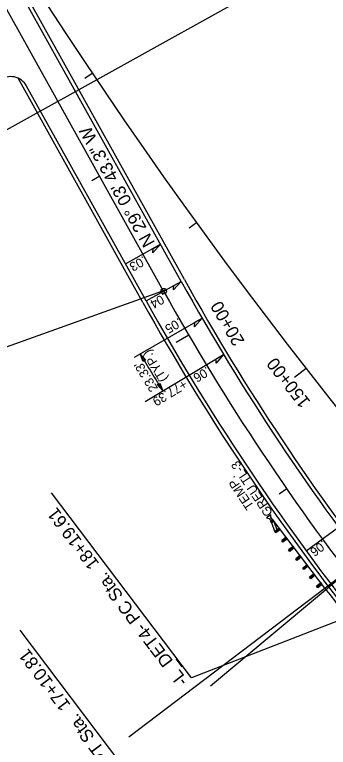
# Model space of a CAD drawing. Extents: x 473658 to 481584, y 489119 to 506230.
# Drawn here: x 476198.9 to 476370.9, y 500835 to 501237.1 of the extents above; entities that cross this region are included whole.
import ezdxf

# ---------------------------------------------------------------- set-up
doc = ezdxf.new("R2010")
doc.units = 0
for name, color, linetype in [('Prop EOT', 7, 'Continuous'), ('Prop Guardrail', 7, 'Continuous'), ('Prop Guardrail Anchor Unit CELL', 7, 'Continuous'), ('Prop Horizontal Alignment', 7, 'Continuous'), ('Prop Horizontal Alignment Direction Label', 7, 'Continuous'), ('Prop Horizontal Alignment Station Label', 7, 'Continuous'), ('Prop Horizontal Alignment Tick Label', 7, 'Continuous'), ('Prop Horizontal Alignment Tick Large', 7, 'Continuous'), ('Prop Horizontal Alignment Tick Small', 7, 'Continuous'), ('Prop Paved Shoulder', 7, 'Continuous'), ('Prop Superelevation  Arrow CELL', 7, 'Continuous'), ('Prop Superelevation Label', 7, 'Continuous'), ('Scratch_Level_5', 7, 'Continuous'), ('Scratch_Level_6', 7, 'Continuous'), ('Sheet Plan And Profile CELL', 7, 'Continuous')]:
    doc.layers.add(name, color=color, linetype=linetype)

msp = doc.modelspace()

# ---------------------------------------------------------------- linework, layer by layer
at = {"layer": 'Prop EOT'}
for p, q in [((476290.24, 501090.74), (475837.09, 501906.16)), ((476271.01, 501080.05), (476205.48, 501197.96))]:
    msp.add_line(p, q, dxfattribs=at)
for centre, radius, start, end in [((476196.74, 501193.11), 10, 29.062, 127.5691), ((477416.95, 501716.88), 1289, 209.06204, 218.24077), ((477416.95, 501716.88), 1311, 209.06204, 218.24077)]:
    msp.add_arc(centre, radius, start, end, dxfattribs=at)
at = {"layer": 'Prop Guardrail'}
msp.add_arc((477416.95, 501716.88), 1315, 217.16826, 218.24077, dxfattribs=at)
at = {"layer": 'Prop Guardrail Anchor Unit CELL'}
for p, q in [((476339.5, 500962.72), (476337.12, 500960.99)), ((476339.5, 500961.27), (476339.5, 500962.72)), ((476337.12, 500960.99), (476338.51, 500960.54)), ((476338.51, 500960.54), (476339.72, 500958.89)), ((476340.48, 500960.03), (476339.29, 500959.12)), ((476339.29, 500959.12), (476341.09, 500959.24)), ((476339.89, 500958.33), (476339.29, 500959.12)), ((476340.7, 500959.61), (476339.5, 500961.27)), ((476339.89, 500958.33), (476339.59, 500958.73)), ((476339.72, 500958.89), (476340.21, 500959.25)), ((476340.48, 500960.03), (476339.89, 500958.33)), ((476341.09, 500959.24), (476339.89, 500958.33)), ((476340.21, 500959.25), (476340.7, 500959.61)), ((476369.07, 500922.41), (476340.78, 500959.63)), ((476342.83, 500954.41), (476341.09, 500959.24)), ((476341.61, 500953.48), (476339.89, 500958.33)), ((476344.05, 500955.33), (476341.61, 500953.48)), ((476344.66, 500954.54), (476342.22, 500952.68)), ((476344.66, 500954.54), (476342.83, 500954.41)), ((476343.44, 500953.61), (476344.05, 500955.33)), ((476341.61, 500953.48), (476343.44, 500953.61)), ((476342.22, 500952.68), (476341.61, 500953.48)), ((476342.83, 500954.41), (476342.22, 500952.68)), ((476343.44, 500953.61), (476342.83, 500954.41)), ((476347.86, 500950.32), (476345.48, 500948.5)), ((476345.48, 500948.5), (476347.27, 500948.61)), ((476346.08, 500947.71), (476345.48, 500948.5)), ((476348.47, 500949.52), (476346.08, 500947.71)), ((476346.67, 500949.41), (476346.08, 500947.71)), ((476348.47, 500949.52), (476346.67, 500949.41)), ((476347.27, 500948.61), (476346.67, 500949.41)), ((476347.27, 500948.61), (476347.86, 500950.32)), ((476351.68, 500945.3), (476349.18, 500943.4)), ((476349.18, 500943.4), (476351.03, 500943.55)), ((476349.78, 500942.6), (476349.18, 500943.4)), ((476352.28, 500944.5), (476349.78, 500942.6)), ((476350.43, 500944.35), (476349.78, 500942.6)), ((476352.28, 500944.5), (476350.43, 500944.35)), ((476351.03, 500943.55), (476350.43, 500944.35)), ((476351.03, 500943.55), (476351.68, 500945.3)), ((476355.49, 500940.28), (476353.07, 500938.45)), ((476353.07, 500938.45), (476354.88, 500938.57)), ((476353.68, 500937.65), (476353.07, 500938.45)), ((476356.09, 500939.49), (476353.68, 500937.65)), ((476354.28, 500939.36), (476353.68, 500937.65)), ((476356.09, 500939.49), (476354.28, 500939.36)), ((476354.88, 500938.57), (476354.28, 500939.36)), ((476354.88, 500938.57), (476355.49, 500940.28)), ((476356.09, 500939.49), (476355.49, 500940.28)), ((476359.3, 500935.26), (476356.87, 500933.42)), ((476359.91, 500934.47), (476357.48, 500932.62)), ((476359.91, 500934.47), (476358.09, 500934.34)), ((476358.69, 500933.55), (476359.3, 500935.26)), ((476356.87, 500933.42), (476358.69, 500933.55)), ((476357.48, 500932.62), (476356.87, 500933.42)), ((476358.09, 500934.34), (476357.48, 500932.62)), ((476358.69, 500933.55), (476358.09, 500934.34)), ((476363.11, 500930.25), (476360.68, 500928.4)), ((476360.68, 500928.4), (476362.5, 500928.53)), ((476361.29, 500927.6), (476360.68, 500928.4)), ((476363.72, 500929.45), (476361.29, 500927.6)), ((476361.9, 500929.32), (476361.29, 500927.6)), ((476363.72, 500929.45), (476361.9, 500929.32)), ((476362.5, 500928.53), (476361.9, 500929.32)), ((476362.5, 500928.53), (476363.11, 500930.25)), ((476366.93, 500925.23), (476364.54, 500923.42)), ((476364.54, 500923.42), (476366.34, 500923.53)), ((476365.14, 500922.62), (476364.54, 500923.42)), ((476367.53, 500924.43), (476365.14, 500922.62)), ((476365.73, 500924.32), (476365.14, 500922.62)), ((476366.93, 500925.23), (476365.73, 500924.32)), ((476365.73, 500924.32), (476367.53, 500924.43)), ((476366.34, 500923.53), (476365.73, 500924.32)), ((476366.34, 500923.53), (476366.93, 500925.23)), ((476367.53, 500924.43), (476366.93, 500925.23))]:
    msp.add_line(p, q, dxfattribs=at)
at = {"layer": 'Prop Horizontal Alignment'}
msp.add_line((476280.62, 501085.39), (475827.47, 501900.81), dxfattribs=at)
for centre, radius, start, end in [((478615.62, 502799.59), 2860, 203.81642, 228.24762), ((477416.95, 501716.88), 1300, 209.06204, 218.24077)]:
    msp.add_arc(centre, radius, start, end, dxfattribs=at)
at = {"layer": 'Prop Horizontal Alignment Station Label'}
for p, q in [((476281.93, 501086.12), (476143.16, 501036.5)), ((476295.9, 500873.14), (476219.07, 500974.65)), ((476395.9, 500912.22), (476295.9, 500873.14)), ((476281.48, 500794.12), (476201.88, 500899.28))]:
    msp.add_line(p, q, dxfattribs=at)
msp.add_circle((476280.62, 501085.39), 1.5, dxfattribs=at)
at = {"layer": 'Prop Horizontal Alignment Tick Large'}
for p, q in [((476294.42, 501061.18), (476287.51, 501057.14)), ((476358.7, 501042.92), (476352.38, 501038))]:
    msp.add_line(p, q, dxfattribs=at)
at = {"layer": 'Prop Horizontal Alignment Tick Small'}
for p, q in [((476241.47, 501204.91), (476237.32, 501202.12)), ((476245.59, 501148.44), (476241.22, 501146.01)), ((476298.67, 501122.89), (476294.62, 501119.96)), ((476348.13, 500976.85), (476344.02, 500974.01))]:
    msp.add_line(p, q, dxfattribs=at)
at = {"layer": 'Prop Paved Shoulder'}
for p, q in [((476291.99, 501091.71), (475838.84, 501907.13)), ((476269.26, 501079.08), (476200.82, 501202.24))]:
    msp.add_line(p, q, dxfattribs=at)
for radius in [1287, 1313]:
    msp.add_arc((477416.95, 501716.88), radius, 209.06204, 218.24077, dxfattribs=at)
at = {"layer": 'Prop Superelevation  Arrow CELL'}
for points in [[(476278.91, 501111.12), (476274.64, 501106.46), (476274.87, 501108.87)], [(476290.24, 501090.73), (476285.97, 501086.06), (476286.2, 501088.48)], [(476301.66, 501070.61), (476297.47, 501065.87), (476297.66, 501068.29)], [(476269.47, 501046.74), (476267.8, 501050.99), (476270.83, 501047.53), (476269.85, 501047.61)], [(476313.44, 501050.7), (476309.34, 501045.89), (476309.48, 501048.31)], [(476278.5, 501034.87), (476280.18, 501030.62), (476277.14, 501034.07), (476278.12, 501033.99)]]:
    msp.add_lwpolyline(points, close=True, dxfattribs=at)
at = {"layer": 'Prop Superelevation Label'}
for p, q in [((476259.68, 501100.43), (476278.91, 501111.12)), ((476271.01, 501080.04), (476290.24, 501090.73)), ((476264.66, 501049.17), (476301.66, 501070.61)), ((476270.51, 501024.78), (476313.44, 501050.7)), ((476358.8, 500942.89), (476376.56, 500955.88))]:
    msp.add_line(p, q, dxfattribs=at)
msp.add_arc((477289.17, 501657.72), 1187.99, 210.71181, 211.86131, dxfattribs=at)
at = {"layer": 'Scratch_Level_5'}
msp.add_line((476188.79, 501170.82), (476353.8, 501262.52), dxfattribs=at)
at = {"layer": 'Scratch_Level_6'}
msp.add_line((476261.46, 500840.89), (476500.52, 501022.13), dxfattribs=at)
at = {"layer": 'Sheet Plan And Profile CELL'}
msp.add_line((476306.41, 500868.88), (476536.56, 501061.31), dxfattribs=at)

# ---------------------------------------------------------------- texts
at = {"layer": 'Prop Guardrail Anchor Unit CELL'}
for s, p in [('GREU TL-3', (476340.78, 500963.77)), ('TEMP. ', (476330.43, 500967.47))]:
    msp.add_text(s, height=5, rotation=123.6936, dxfattribs=at).set_placement(p)
at = {"layer": 'Prop Horizontal Alignment Direction Label'}
msp.add_text('N 29%%d 03\' 43.3" W', height=7, rotation=119.062, dxfattribs=at).set_placement((476276, 501111.97))
at = {"layer": 'Prop Horizontal Alignment Station Label'}
for s, p in [('-L_DET4- PC Sta.  18+19.61', (476294.27, 500871.61)), ('-L_DET4- PT Sta.  17+10.81', (476277.94, 500794.9))]:
    msp.add_text(s, height=7, rotation=127.1236, dxfattribs=at).set_placement(p)
at = {"layer": 'Prop Horizontal Alignment Tick Label'}
for s, rotation, p in [('20+00', 120.2905, (476325.22, 501057.98)), ('150+00', 127.8955, (476361.45, 501024.73))]:
    msp.add_text(s, height=7, rotation=rotation, dxfattribs=at).set_placement(p)
at = {"layer": 'Prop Superelevation Label'}
for s, rotation, p in [('.03', 209.062, (476269.47, 501104.83)), ('.04', 209.0621, (476280.78, 501084.42)), ('.05', 210.0908, (476288.82, 501070.84)), ('(TYP.)', 121.2954, (476283.03, 501037.29)), ("23.33'", 121.2954, (476277.73, 501031.99)), ('.06', 211.1191, (476304.31, 501044.12)), ('+77.39', 211.2954, (476291.64, 501036.97)), ('.06', 216.184, (476367.88, 500948.95))]:
    msp.add_text(s, height=5, rotation=rotation, dxfattribs=at).set_placement(p)

doc.saveas('drawing.dxf')
